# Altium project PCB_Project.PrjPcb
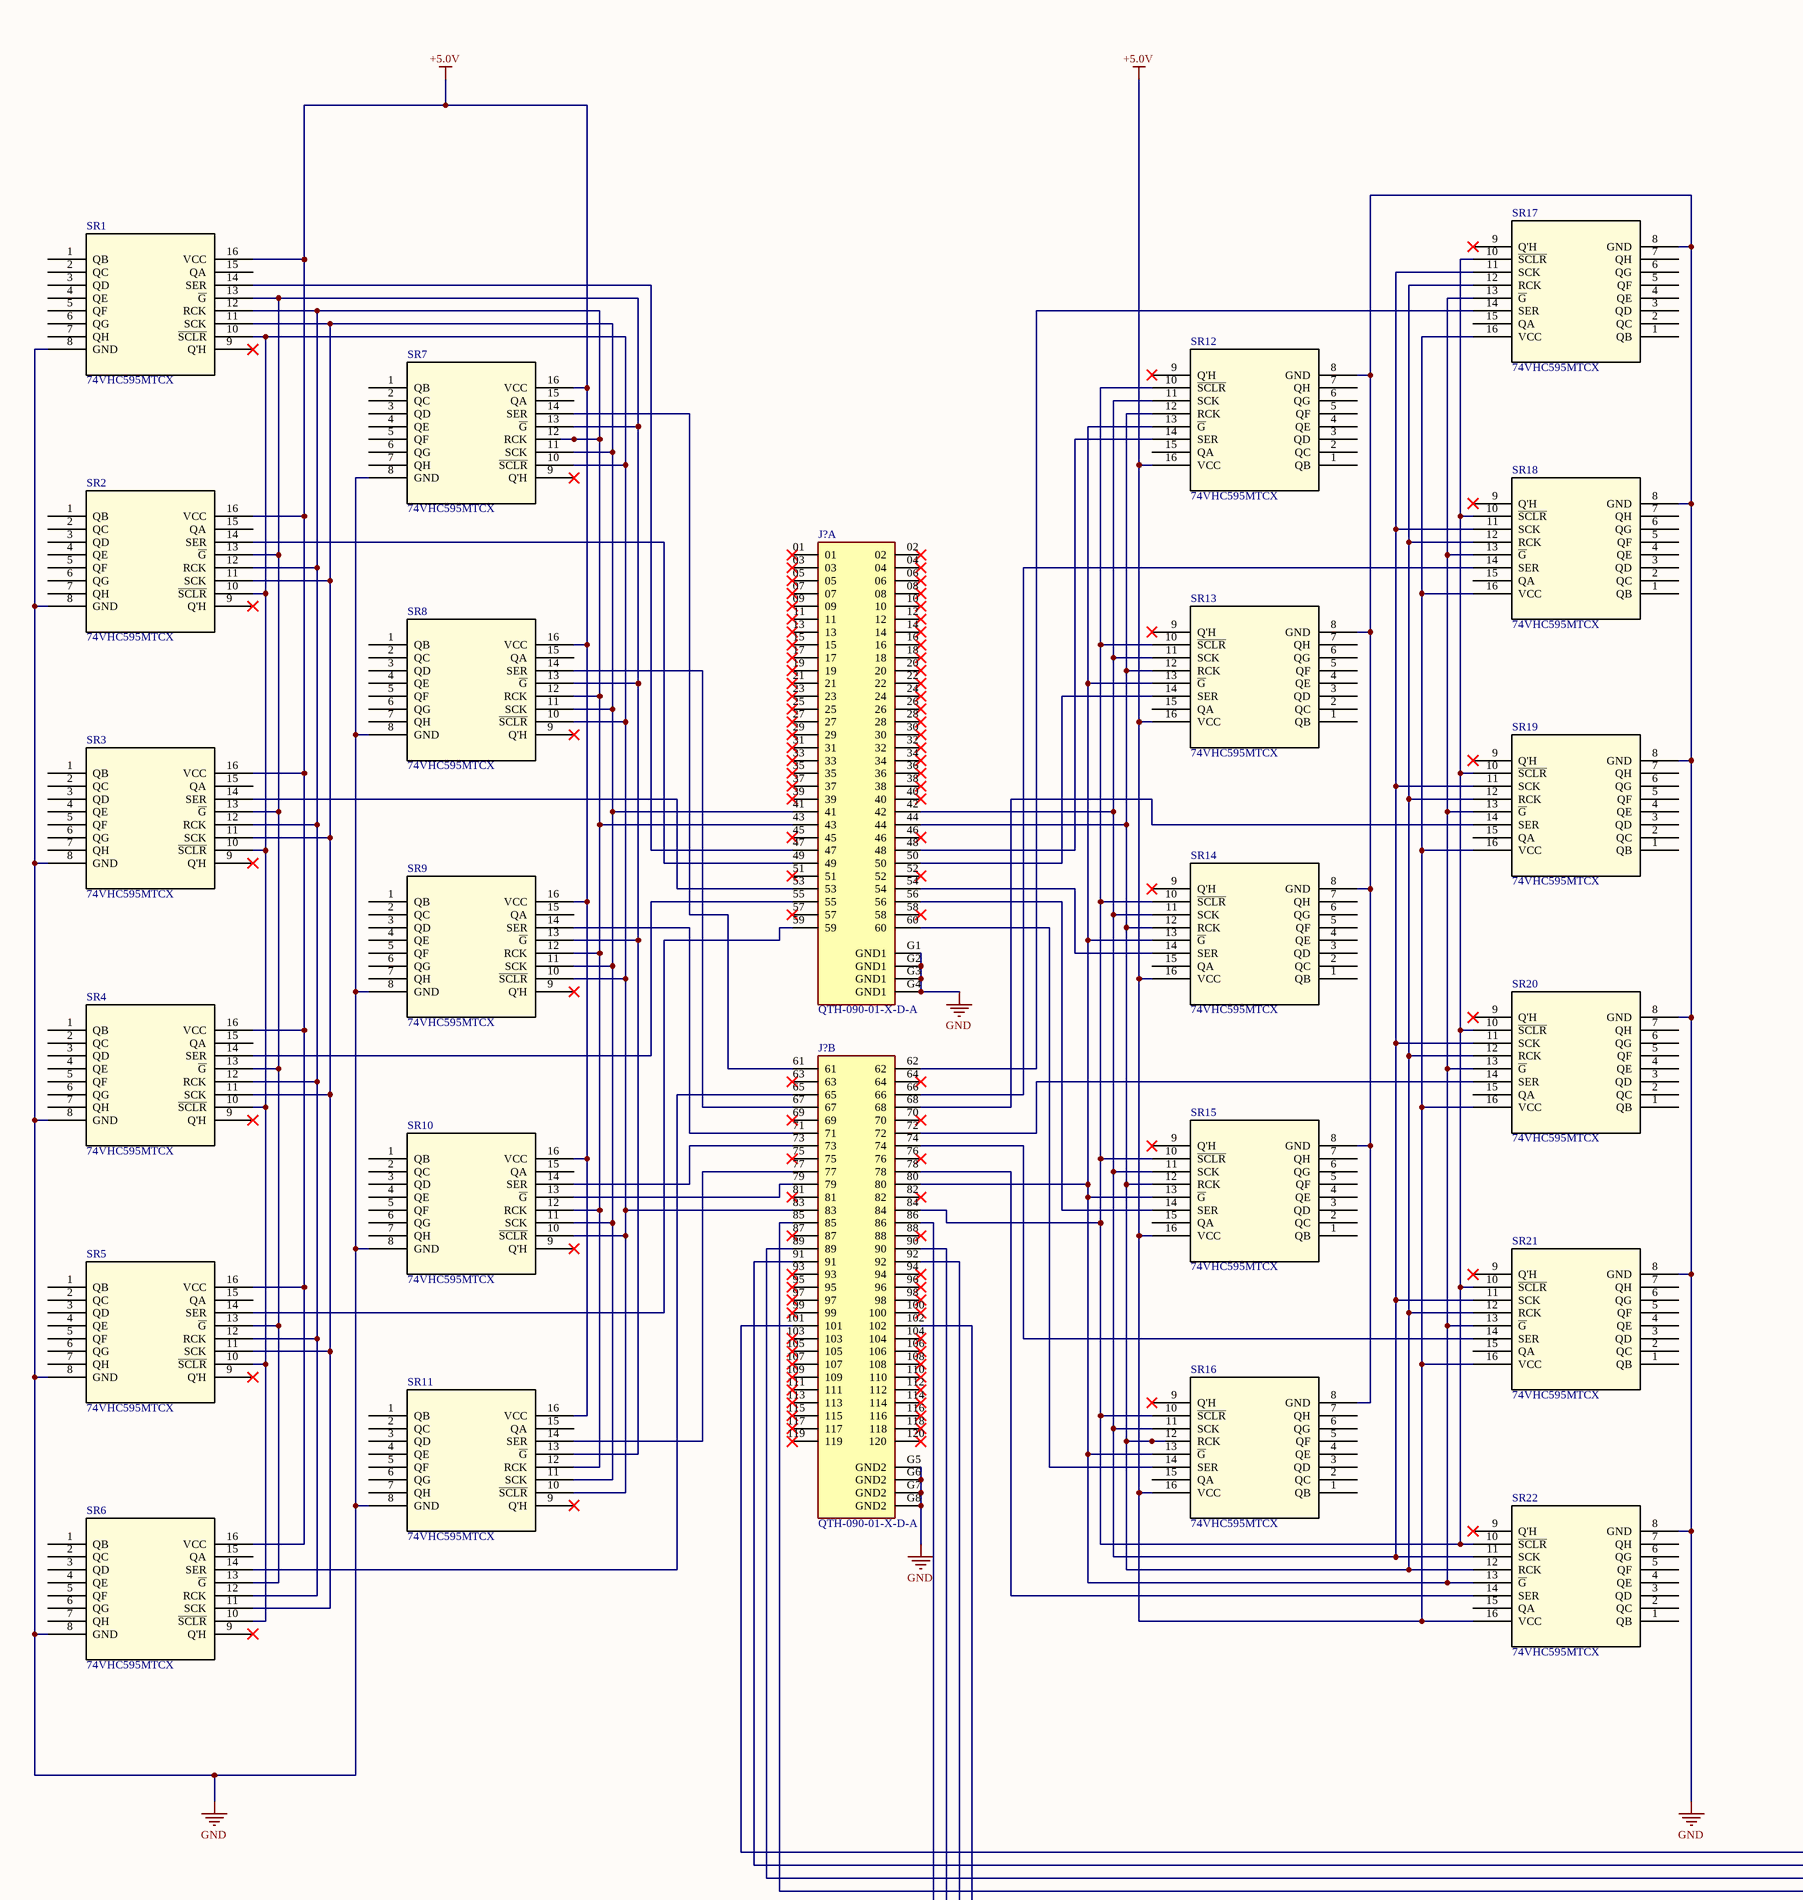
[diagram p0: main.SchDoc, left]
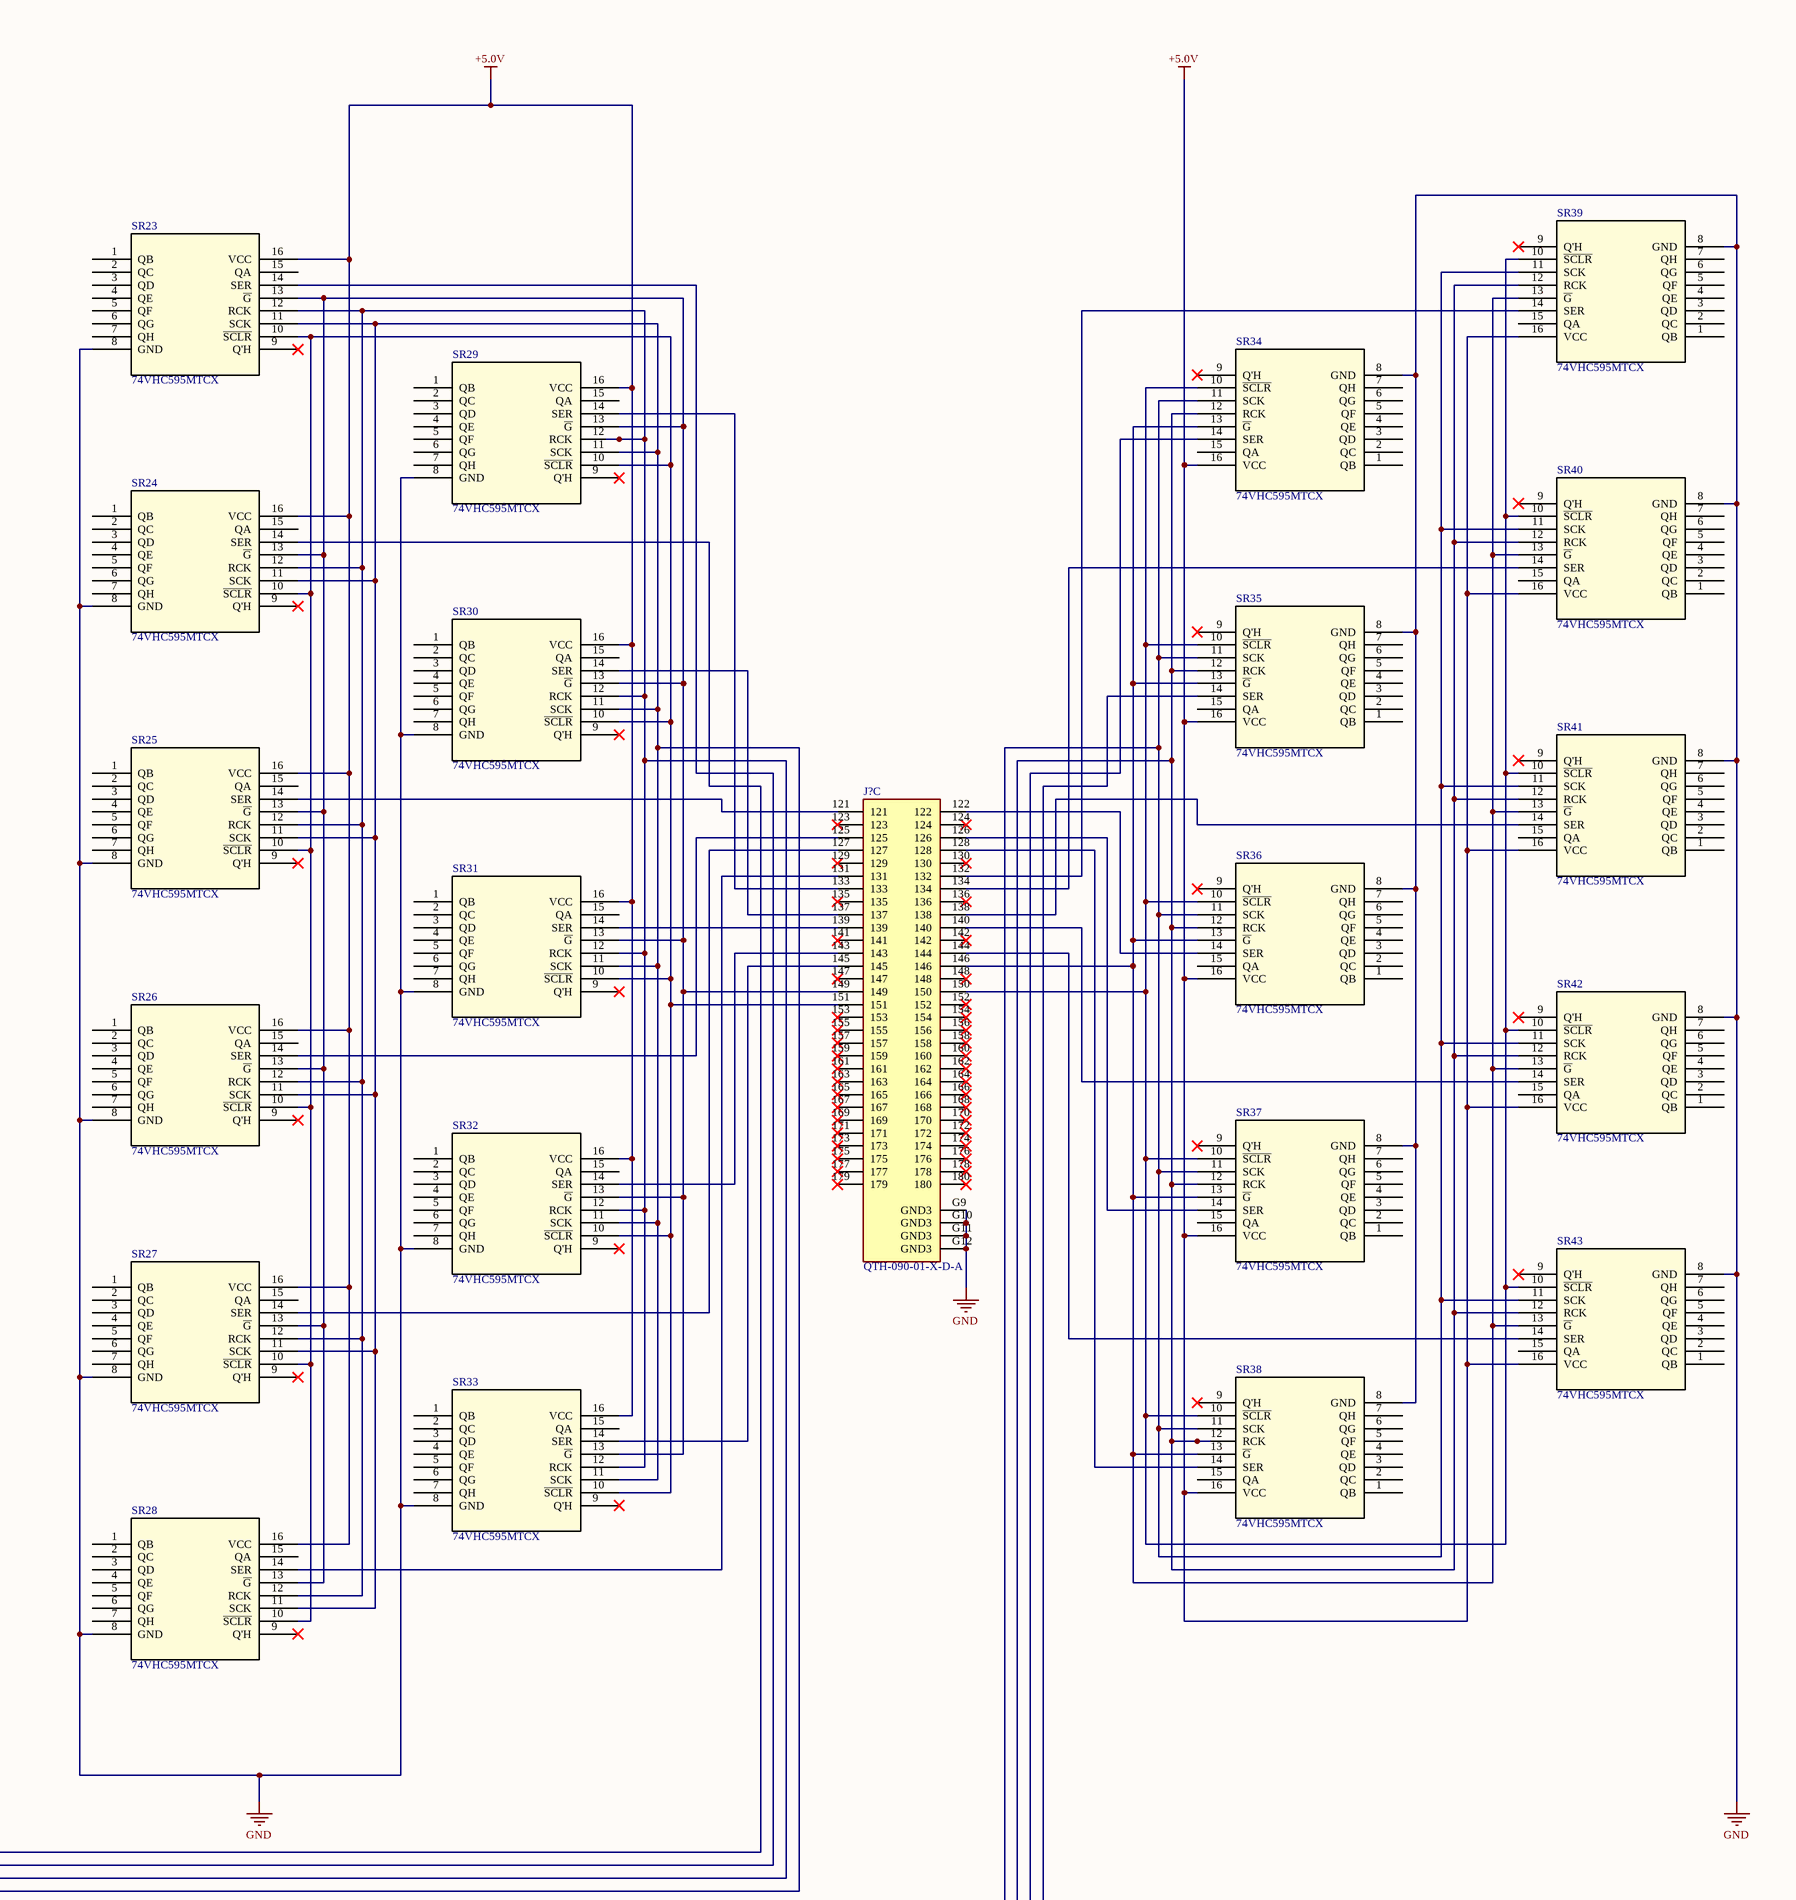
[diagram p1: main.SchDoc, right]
1 sheet, 46 parts. Net scope: global (net labels, ports and power ports of the same name join across sheets).
Board file: PCB1.PcbDoc

## Sheet main.SchDoc
size D; SheetNumber: 1; SheetTotal: 1

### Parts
(Parts that share a designator on the sheet are numbered #1, #2 ... from top to bottom, then left to right.)
J?#1  QTH-090-01-X-D-A  [SAMTEC_QTH-090-01-X-D-A]  (part A of 3)
J?#2  QTH-090-01-X-D-A  [SAMTEC_QTH-090-01-X-D-A]  (part C of 3)
J?#3  QTH-090-01-X-D-A  [SAMTEC_QTH-090-01-X-D-A]  (part B of 3)
SR1  74VHC595MTCX  [TSSOP16_5X4P5_ONS]
SR2  74VHC595MTCX  [TSSOP16_5X4P5_ONS]
SR3  74VHC595MTCX  [TSSOP16_5X4P5_ONS]
SR4  74VHC595MTCX  [TSSOP16_5X4P5_ONS]
SR5  74VHC595MTCX  [TSSOP16_5X4P5_ONS]
SR6  74VHC595MTCX  [TSSOP16_5X4P5_ONS]
SR7  74VHC595MTCX  [TSSOP16_5X4P5_ONS]
SR8  74VHC595MTCX  [TSSOP16_5X4P5_ONS]
SR9  74VHC595MTCX  [TSSOP16_5X4P5_ONS]
SR10  74VHC595MTCX  [TSSOP16_5X4P5_ONS]
SR11  74VHC595MTCX  [TSSOP16_5X4P5_ONS]
SR12  74VHC595MTCX  [TSSOP16_5X4P5_ONS]
SR13  74VHC595MTCX  [TSSOP16_5X4P5_ONS]
SR14  74VHC595MTCX  [TSSOP16_5X4P5_ONS]
SR15  74VHC595MTCX  [TSSOP16_5X4P5_ONS]
SR16  74VHC595MTCX  [TSSOP16_5X4P5_ONS]
SR17  74VHC595MTCX  [TSSOP16_5X4P5_ONS]
SR18  74VHC595MTCX  [TSSOP16_5X4P5_ONS]
SR19  74VHC595MTCX  [TSSOP16_5X4P5_ONS]
SR20  74VHC595MTCX  [TSSOP16_5X4P5_ONS]
SR21  74VHC595MTCX  [TSSOP16_5X4P5_ONS]
SR22  74VHC595MTCX  [TSSOP16_5X4P5_ONS]
SR23  74VHC595MTCX  [TSSOP16_5X4P5_ONS]
SR24  74VHC595MTCX  [TSSOP16_5X4P5_ONS]
SR25  74VHC595MTCX  [TSSOP16_5X4P5_ONS]
SR26  74VHC595MTCX  [TSSOP16_5X4P5_ONS]
SR27  74VHC595MTCX  [TSSOP16_5X4P5_ONS]
SR28  74VHC595MTCX  [TSSOP16_5X4P5_ONS]
SR29  74VHC595MTCX  [TSSOP16_5X4P5_ONS]
SR30  74VHC595MTCX  [TSSOP16_5X4P5_ONS]
SR31  74VHC595MTCX  [TSSOP16_5X4P5_ONS]
SR32  74VHC595MTCX  [TSSOP16_5X4P5_ONS]
SR33  74VHC595MTCX  [TSSOP16_5X4P5_ONS]
SR34  74VHC595MTCX  [TSSOP16_5X4P5_ONS]
SR35  74VHC595MTCX  [TSSOP16_5X4P5_ONS]
SR36  74VHC595MTCX  [TSSOP16_5X4P5_ONS]
SR37  74VHC595MTCX  [TSSOP16_5X4P5_ONS]
SR38  74VHC595MTCX  [TSSOP16_5X4P5_ONS]
SR39  74VHC595MTCX  [TSSOP16_5X4P5_ONS]
SR40  74VHC595MTCX  [TSSOP16_5X4P5_ONS]
SR41  74VHC595MTCX  [TSSOP16_5X4P5_ONS]
SR42  74VHC595MTCX  [TSSOP16_5X4P5_ONS]
SR43  74VHC595MTCX  [TSSOP16_5X4P5_ONS]

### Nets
+5.0V: SR1.16(VCC) SR2.16(VCC) SR3.16(VCC) SR4.16(VCC) SR5.16(VCC) SR6.16(VCC) SR7.16(VCC) SR8.16(VCC) SR9.16(VCC) SR10.16(VCC) SR11.16(VCC) SR12.16(VCC) SR13.16(VCC) SR14.16(VCC) SR15.16(VCC) SR16.16(VCC) SR17.16(VCC) SR18.16(VCC) SR19.16(VCC) SR20.16(VCC) SR21.16(VCC) SR22.16(VCC) SR23.16(VCC) SR24.16(VCC) SR25.16(VCC) SR26.16(VCC) SR27.16(VCC) SR28.16(VCC) SR29.16(VCC) SR30.16(VCC) SR31.16(VCC) SR32.16(VCC) SR33.16(VCC) SR34.16(VCC) SR35.16(VCC) SR36.16(VCC) SR37.16(VCC) SR38.16(VCC) SR39.16(VCC) SR40.16(VCC) SR41.16(VCC) SR42.16(VCC) SR43.16(VCC)
GND: J?#1.G1(GND1) J?#1.G2(GND1) J?#1.G3(GND1) J?#1.G4(GND1) J?#2.G9(GND3) J?#2.G10(GND3) J?#2.G11(GND3) J?#2.G12(GND3) J?#3.G5(GND2) J?#3.G6(GND2) J?#3.G7(GND2) J?#3.G8(GND2) SR1.8(GND) SR2.8(GND) SR3.8(GND) SR4.8(GND) SR5.8(GND) SR6.8(GND) SR7.8(GND) SR8.8(GND) SR9.8(GND) SR10.8(GND) SR11.8(GND) SR12.8(GND) SR13.8(GND) SR14.8(GND) SR15.8(GND) SR16.8(GND) SR17.8(GND) SR18.8(GND) SR19.8(GND) SR20.8(GND) SR21.8(GND) SR22.8(GND) SR23.8(GND) SR24.8(GND) SR25.8(GND) SR26.8(GND) SR27.8(GND) SR28.8(GND) SR29.8(GND) SR30.8(GND) SR31.8(GND) SR32.8(GND) SR33.8(GND) SR34.8(GND) SR35.8(GND) SR36.8(GND) SR37.8(GND) SR38.8(GND) SR39.8(GND) SR40.8(GND) SR41.8(GND) SR42.8(GND) SR43.8(GND)
NetJ?#1_41: J?#1.41 SR1.11(SCK) SR2.11(SCK) SR3.11(SCK) SR4.11(SCK) SR5.11(SCK) SR6.11(SCK) SR7.11(SCK) SR8.11(SCK) SR9.11(SCK) SR10.11(SCK) SR11.11(SCK)
NetJ?#1_42: J?#1.42 SR12.11(SCK) SR13.11(SCK) SR14.11(SCK) SR15.11(SCK) SR16.11(SCK) SR17.11(SCK) SR18.11(SCK) SR19.11(SCK) SR20.11(SCK) SR21.11(SCK) SR22.11(SCK)
NetJ?#1_43: J?#1.43 SR1.12(RCK) SR2.12(RCK) SR3.12(RCK) SR4.12(RCK) SR5.12(RCK) SR6.12(RCK) SR7.12(RCK) SR8.12(RCK) SR9.12(RCK) SR10.12(RCK) SR11.12(RCK)
NetJ?#1_44: J?#1.44 SR12.12(RCK) SR13.12(RCK) SR14.12(RCK) SR15.12(RCK) SR16.12(RCK) SR17.12(RCK) SR18.12(RCK) SR19.12(RCK) SR20.12(RCK) SR21.12(RCK) SR22.12(RCK)
NetJ?#1_47: J?#1.47 SR1.14(SER)
NetJ?#1_48: J?#1.48 SR12.14(SER)
NetJ?#1_49: J?#1.49 SR2.14(SER)
NetJ?#1_50: J?#1.50 SR13.14(SER)
NetJ?#1_53: J?#1.53 SR3.14(SER)
NetJ?#1_54: J?#1.54 SR14.14(SER)
NetJ?#1_55: J?#1.55 SR4.14(SER)
NetJ?#1_56: J?#1.56 SR15.14(SER)
NetJ?#1_59: J?#1.59 SR5.14(SER)
NetJ?#1_60: J?#1.60 SR16.14(SER)
NetJ?#2_121: J?#2.121 SR25.14(SER)
NetJ?#2_122: J?#2.122 SR36.14(SER)
NetJ?#2_125: J?#2.125 SR26.14(SER)
NetJ?#2_126: J?#2.126 SR37.14(SER)
NetJ?#2_127: J?#2.127 SR27.14(SER)
NetJ?#2_128: J?#2.128 SR38.14(SER)
NetJ?#2_131: J?#2.131 SR28.14(SER)
NetJ?#2_132: J?#2.132 SR39.14(SER)
NetJ?#2_133: J?#2.133 SR29.14(SER)
NetJ?#2_134: J?#2.134 SR40.14(SER)
NetJ?#2_137: J?#2.137 SR30.14(SER)
NetJ?#2_138: J?#2.138 SR41.14(SER)
NetJ?#2_139: J?#2.139 SR31.14(SER)
NetJ?#2_140: J?#2.140 SR42.14(SER)
NetJ?#2_143: J?#2.143 SR32.14(SER)
NetJ?#2_144: J?#2.144 SR43.14(SER)
NetJ?#2_145: J?#2.145 SR33.14(SER)
NetJ?#2_146: J?#2.146 SR34.13(~{G}) SR35.13(~{G}) SR36.13(~{G}) SR37.13(~{G}) SR38.13(~{G}) SR39.13(~{G}) SR40.13(~{G}) SR41.13(~{G}) SR42.13(~{G}) SR43.13(~{G})
NetJ?#2_149: J?#2.149 SR23.13(~{G}) SR24.13(~{G}) SR25.13(~{G}) SR26.13(~{G}) SR27.13(~{G}) SR28.13(~{G}) SR29.13(~{G}) SR30.13(~{G}) SR31.13(~{G}) SR32.13(~{G}) SR33.13(~{G})
NetJ?#2_150: J?#2.150 SR34.10(~{SCLR}) SR35.10(~{SCLR}) SR36.10(~{SCLR}) SR37.10(~{SCLR}) SR38.10(~{SCLR}) SR39.10(~{SCLR}) SR40.10(~{SCLR}) SR41.10(~{SCLR}) SR42.10(~{SCLR}) SR43.10(~{SCLR})
NetJ?#2_151: J?#2.151 SR23.10(~{SCLR}) SR24.10(~{SCLR}) SR25.10(~{SCLR}) SR26.10(~{SCLR}) SR27.10(~{SCLR}) SR28.10(~{SCLR}) SR29.10(~{SCLR}) SR30.10(~{SCLR}) SR31.10(~{SCLR}) SR32.10(~{SCLR}) SR33.10(~{SCLR})
NetJ?#3_61: J?#3.61 SR7.14(SER)
NetJ?#3_62: J?#3.62 SR17.14(SER)
NetJ?#3_65: J?#3.65 SR6.14(SER)
NetJ?#3_66: J?#3.66 SR18.14(SER)
NetJ?#3_67: J?#3.67 SR8.14(SER)
NetJ?#3_68: J?#3.68 SR19.14(SER)
NetJ?#3_71: J?#3.71 SR9.14(SER)
NetJ?#3_72: J?#3.72 SR20.14(SER)
NetJ?#3_73: J?#3.73 SR10.14(SER)
NetJ?#3_74: J?#3.74 SR21.14(SER)
NetJ?#3_77: J?#3.77 SR11.14(SER)
NetJ?#3_78: J?#3.78 SR22.14(SER)
NetJ?#3_79: J?#3.79 SR10.13(~{G})
NetJ?#3_80: J?#3.80 SR12.13(~{G}) SR13.13(~{G}) SR14.13(~{G}) SR15.13(~{G}) SR16.13(~{G}) SR17.13(~{G}) SR18.13(~{G}) SR19.13(~{G}) SR20.13(~{G}) SR21.13(~{G}) SR22.13(~{G})
NetJ?#3_83: J?#3.83 SR1.10(~{SCLR}) SR2.10(~{SCLR}) SR3.10(~{SCLR}) SR4.10(~{SCLR}) SR5.10(~{SCLR}) SR6.10(~{SCLR}) SR7.10(~{SCLR}) SR8.10(~{SCLR}) SR9.10(~{SCLR}) SR10.10(~{SCLR}) SR11.10(~{SCLR})
NetJ?#3_84: J?#3.84 SR12.10(~{SCLR}) SR13.10(~{SCLR}) SR14.10(~{SCLR}) SR15.10(~{SCLR}) SR16.10(~{SCLR}) SR17.10(~{SCLR}) SR18.10(~{SCLR}) SR19.10(~{SCLR}) SR20.10(~{SCLR}) SR21.10(~{SCLR}) SR22.10(~{SCLR})
NetJ?#3_85: J?#3.85 SR23.11(SCK) SR24.11(SCK) SR25.11(SCK) SR26.11(SCK) SR27.11(SCK) SR28.11(SCK) SR29.11(SCK) SR30.11(SCK) SR31.11(SCK) SR32.11(SCK) SR33.11(SCK)
NetJ?#3_86: J?#3.86 SR34.11(SCK) SR35.11(SCK) SR36.11(SCK) SR37.11(SCK) SR38.11(SCK) SR39.11(SCK) SR40.11(SCK) SR41.11(SCK) SR42.11(SCK) SR43.11(SCK)
NetJ?#3_89: J?#3.89 SR23.12(RCK) SR24.12(RCK) SR25.12(RCK) SR26.12(RCK) SR27.12(RCK) SR28.12(RCK) SR29.12(RCK) SR30.12(RCK) SR31.12(RCK) SR32.12(RCK) SR33.12(RCK)
NetJ?#3_90: J?#3.90 SR34.12(RCK) SR35.12(RCK) SR36.12(RCK) SR37.12(RCK) SR38.12(RCK) SR39.12(RCK) SR40.12(RCK) SR41.12(RCK) SR42.12(RCK) SR43.12(RCK)
NetJ?#3_91: J?#3.91 SR23.14(SER)
NetJ?#3_92: J?#3.92 SR34.14(SER)
NetJ?#3_101: J?#3.101 SR24.14(SER)
NetJ?#3_102: J?#3.102 SR35.14(SER)
NetSR1_13: SR1.13(~{G}) SR2.13(~{G}) SR3.13(~{G}) SR4.13(~{G}) SR5.13(~{G}) SR6.13(~{G}) SR7.13(~{G}) SR8.13(~{G}) SR9.13(~{G}) SR11.13(~{G})

Not connected (* = marked no-connect by the designer): J?#1 01* 02* 03* 04* 05* 06* 07* 08* 09* 10* 11* 12* 13* 14* 15* 16* 17* 18* 19* 20* 21* 22* 23* 24* 25* 26* 27* 28* 29* 30* 31* 32* 33* 34* 35* 36* 37* 38* 39* 40* 45* 46* 51* 52* 57* 58*; J?#2 123* 124* 129* 130* 135* 136* 141* 142* 147* 148* 152* 153* 154* 155* 156* 157* 158* 159* 160* 161* 162* 163* 164* 165* 166* 167* 168* 169* 170* 171* 172* 173* 174* 175* 176* 177* 178* 179* 180*; J?#3 63* 64* 69* 70* 75* 76* 81* 82* 87* 88* 93* 94* 95* 96* 97* 98* 99* 100* 103* 104* 105* 106* 107* 108* 109* 110* 111* 112* 113* 114* 115* 116* 117* 118* 119* 120*; SR1 1(QB) 2(QC) 3(QD) 4(QE) 5(QF) 6(QG) 7(QH) 9(Q'H)* 15(QA); SR2 1(QB) 2(QC) 3(QD) 4(QE) 5(QF) 6(QG) 7(QH) 9(Q'H)* 15(QA); SR3 1(QB) 2(QC) 3(QD) 4(QE) 5(QF) 6(QG) 7(QH) 9(Q'H)* 15(QA); SR4 1(QB) 2(QC) 3(QD) 4(QE) 5(QF) 6(QG) 7(QH) 9(Q'H)* 15(QA); SR5 1(QB) 2(QC) 3(QD) 4(QE) 5(QF) 6(QG) 7(QH) 9(Q'H)* 15(QA); SR6 1(QB) 2(QC) 3(QD) 4(QE) 5(QF) 6(QG) 7(QH) 9(Q'H)* 15(QA); SR7 1(QB) 2(QC) 3(QD) 4(QE) 5(QF) 6(QG) 7(QH) 9(Q'H)* 15(QA); SR8 1(QB) 2(QC) 3(QD) 4(QE) 5(QF) 6(QG) 7(QH) 9(Q'H)* 15(QA); SR9 1(QB) 2(QC) 3(QD) 4(QE) 5(QF) 6(QG) 7(QH) 9(Q'H)* 15(QA); SR10 1(QB) 2(QC) 3(QD) 4(QE) 5(QF) 6(QG) 7(QH) 9(Q'H)* 15(QA); SR11 1(QB) 2(QC) 3(QD) 4(QE) 5(QF) 6(QG) 7(QH) 9(Q'H)* 15(QA); SR12 1(QB) 2(QC) 3(QD) 4(QE) 5(QF) 6(QG) 7(QH) 9(Q'H)* 15(QA); SR13 1(QB) 2(QC) 3(QD) 4(QE) 5(QF) 6(QG) 7(QH) 9(Q'H)* 15(QA); SR14 1(QB) 2(QC) 3(QD) 4(QE) 5(QF) 6(QG) 7(QH) 9(Q'H)* 15(QA); SR15 1(QB) 2(QC) 3(QD) 4(QE) 5(QF) 6(QG) 7(QH) 9(Q'H)* 15(QA); SR16 1(QB) 2(QC) 3(QD) 4(QE) 5(QF) 6(QG) 7(QH) 9(Q'H)* 15(QA); SR17 1(QB) 2(QC) 3(QD) 4(QE) 5(QF) 6(QG) 7(QH) 9(Q'H)* 15(QA); SR18 1(QB) 2(QC) 3(QD) 4(QE) 5(QF) 6(QG) 7(QH) 9(Q'H)* 15(QA); SR19 1(QB) 2(QC) 3(QD) 4(QE) 5(QF) 6(QG) 7(QH) 9(Q'H)* 15(QA); SR20 1(QB) 2(QC) 3(QD) 4(QE) 5(QF) 6(QG) 7(QH) 9(Q'H)* 15(QA); SR21 1(QB) 2(QC) 3(QD) 4(QE) 5(QF) 6(QG) 7(QH) 9(Q'H)* 15(QA); SR22 1(QB) 2(QC) 3(QD) 4(QE) 5(QF) 6(QG) 7(QH) 9(Q'H)* 15(QA); SR23 1(QB) 2(QC) 3(QD) 4(QE) 5(QF) 6(QG) 7(QH) 9(Q'H)* 15(QA); SR24 1(QB) 2(QC) 3(QD) 4(QE) 5(QF) 6(QG) 7(QH) 9(Q'H)* 15(QA); SR25 1(QB) 2(QC) 3(QD) 4(QE) 5(QF) 6(QG) 7(QH) 9(Q'H)* 15(QA); SR26 1(QB) 2(QC) 3(QD) 4(QE) 5(QF) 6(QG) 7(QH) 9(Q'H)* 15(QA); SR27 1(QB) 2(QC) 3(QD) 4(QE) 5(QF) 6(QG) 7(QH) 9(Q'H)* 15(QA); SR28 1(QB) 2(QC) 3(QD) 4(QE) 5(QF) 6(QG) 7(QH) 9(Q'H)* 15(QA); SR29 1(QB) 2(QC) 3(QD) 4(QE) 5(QF) 6(QG) 7(QH) 9(Q'H)* 15(QA); SR30 1(QB) 2(QC) 3(QD) 4(QE) 5(QF) 6(QG) 7(QH) 9(Q'H)* 15(QA); SR31 1(QB) 2(QC) 3(QD) 4(QE) 5(QF) 6(QG) 7(QH) 9(Q'H)* 15(QA); SR32 1(QB) 2(QC) 3(QD) 4(QE) 5(QF) 6(QG) 7(QH) 9(Q'H)* 15(QA); SR33 1(QB) 2(QC) 3(QD) 4(QE) 5(QF) 6(QG) 7(QH) 9(Q'H)* 15(QA); SR34 1(QB) 2(QC) 3(QD) 4(QE) 5(QF) 6(QG) 7(QH) 9(Q'H)* 15(QA); SR35 1(QB) 2(QC) 3(QD) 4(QE) 5(QF) 6(QG) 7(QH) 9(Q'H)* 15(QA); SR36 1(QB) 2(QC) 3(QD) 4(QE) 5(QF) 6(QG) 7(QH) 9(Q'H)* 15(QA); SR37 1(QB) 2(QC) 3(QD) 4(QE) 5(QF) 6(QG) 7(QH) 9(Q'H)* 15(QA); SR38 1(QB) 2(QC) 3(QD) 4(QE) 5(QF) 6(QG) 7(QH) 9(Q'H)* 15(QA); SR39 1(QB) 2(QC) 3(QD) 4(QE) 5(QF) 6(QG) 7(QH) 9(Q'H)* 15(QA); SR40 1(QB) 2(QC) 3(QD) 4(QE) 5(QF) 6(QG) 7(QH) 9(Q'H)* 15(QA); SR41 1(QB) 2(QC) 3(QD) 4(QE) 5(QF) 6(QG) 7(QH) 9(Q'H)* 15(QA); SR42 1(QB) 2(QC) 3(QD) 4(QE) 5(QF) 6(QG) 7(QH) 9(Q'H)* 15(QA); SR43 1(QB) 2(QC) 3(QD) 4(QE) 5(QF) 6(QG) 7(QH) 9(Q'H)* 15(QA)

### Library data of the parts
J?#1-J?#3 = QTH-090-01-X-D-A: 180 Position Connector Header, Outer Shroud Contacts Surface Mount Gold; MP: QTH-090-01-H-D-A-TR; MF: Samtec Inc.
SR1-SR43 = 74VHC595MTCX: No Description Available; Mfr_Name: onsemi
